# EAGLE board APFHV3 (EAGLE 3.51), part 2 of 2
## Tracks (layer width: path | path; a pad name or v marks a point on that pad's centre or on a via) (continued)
N$34  (via drill 0.05 pad 0.2) (continued)
  Bottom 0.1: v38.42,9.23 38.42,10.5 38.35,10.58 34,10.58 32.77,11.8 30.02,11.8 29.87,11.95 27.15,11.95 26.97,11.78 24.32,11.78 24.15,11.95 23.2,11.95 22.75,11.5 20.12,11.5 v19.3,12.33
N$35  (via drill 0.05 pad 0.2)
  Top 0.1: BARE_DIE. 38.07,6.2 38.62,6.75 38.62,9 v38.85,9.23 | v20.85,11.83 20.85,12.08
  Bottom 0.1: v38.85,9.23 38.85,10.58 38.65,10.78 34.17,10.78 32.95,12 30.15,12 30,12.15 27.02,12.15 26.85,11.98 24.5,11.98 24.32,12.15 22.97,12.15 22.57,11.75 20.92,11.75 v20.85,11.83
N$38
  Top 0.075: 13.4,0.8 13.4,0.4
N$39
  Top 0.075: 13.4,1.4 13.4,1
N$40
  Top 0.075: 13.9,0.9 13.5,0.9
N$41
  Top 0.075: 12.9,0.9 13.3,0.9
N$42
  Top 0.075: 13.9,18.7 13.5,18.7
N$43
  Top 0.075: 13.4,18.2 13.4,18.6
N$44
  Top 0.075: 12.9,18.7 13.3,18.7
N$45
  Top 0.075: 13.4,19.2 13.4,18.8
N$46
  Top 0.075: 73.2,18.2 73.2,18.6
N$47
  Top 0.075: 73.7,18.7 73.3,18.7
N$48
  Top 0.075: 72.7,18.7 73.1,18.7
N$49
  Top 0.075: 73.2,19.2 73.2,18.8
N$50
  Top 0.075: 73.2,1.23 73.2,1
N$51
  Top 0.075: 73.2,0.4 73.2,0.8
N$52
  Top 0.075: 73.7,0.9 73.3,0.9
N$53
  Top 0.075: 72.7,0.9 73.1,0.9
N$135
  Top 0.1: 39.45,13.1 40.35,13.1 40.35,12.3
NTC
  Top 0.1: 63.35,7.8 63.35,7.45 62.6,6.7 59.88,6.7 59.45,6.28 55,6.28 54.8,6.48 54.12,6.48 52.88,7.73 51.67,7.73 51.55,7.6 51.55,7.33 51.88,7 52.1,7 52.5,6.6 52.5,4.63 52.3,4.43 TR1.
NTC_RET
  Top 0.1: 61.85,7.8 61.85,7.45 61.57,7.18 59.88,7.18 59.2,6.5 55.2,6.5 54.97,6.73 54.2,6.73 52.95,7.98 51.2,7.98 50.7,7.48 50.7,6.1 50.82,5.98 51.55,5.98
RSIB  (via drill 0.05 pad 0.2)
  Top 0.1: 73.3,10.3 72.55,10.3 72.38,10.12 v72.38,9.05 | v60.35,8.48 60.35,7.8 | BARE_DIE.B 41.95,8.53 42.1,8.68 v42.1,8.88
  Bottom 0.1: v42.1,8.88 42.7,8.88 42.88,8.7 50.75,8.7 50.85,8.6 60.22,8.6 v60.35,8.48 60.4,8.43 71.75,8.43 v72.38,9.05
STRIN  (via drill 0.05 pad 0.2)
  Top 0.1: JPA_.1 v72.88,8.3 71.15,8.3 R1. | BARE_DIE.IN 41.65,8.73 v40.1,8.73 | 59.35,7.8 59.2,7.8 v58.97,8.03
  Bottom 0.1: v72.88,8.3 72.35,8.3 72.07,8.03 v58.97,8.03 58.8,8.2 50.3,8.2 50.2,8.3 42.67,8.3 42.62,8.35 42.17,8.35 41.88,8.05 40.25,8.05 40.1,8.2 v40.1,8.73
STRIP  (via drill 0.05 pad 0.2)
  Top 0.1: 73.3,8.8 v72.85,8.8 72.03,8.8 72.03,9 71.55,9.48 71.55,9.5 71.05,9.5 | v59.85,8.28 59.85,7.8 | BARE_DIE.IP 41.65,8.98 v41.02,8.98
  Bottom 0.1: v72.85,8.8 72.45,8.8 71.88,8.23 59.9,8.23 v59.85,8.28 59.82,8.28 59.7,8.4 50.5,8.4 50.4,8.5 42.77,8.5 42.72,8.55 41.45,8.55 41.15,8.25 40.5,8.25 40.38,8.38 40.38,8.85 40.5,8.98 v41.02,8.98
STRN  (via drill 0.05 pad 0.2)
  Top 0.075: 15.07,16.93 15.57,17.43 FE-7.2 | 22.67,16.93 23.17,17.43 FE-6.2 | 30.27,16.93 30.77,17.43 FE-5.2 | 37.88,16.93 38.38,17.43 FE-4.2 | 45.47,16.93 45.97,17.43 FE-3.2 | 53.07,16.93 53.57,17.43 FE-2.2 | 60.67,16.93 61.17,17.43 FE-1.2 | 68.28,16.93 68.78,17.43 FE-0.2 | 18.32,2.68 17.82,2.18 FE-8.2 | 25.92,2.68 25.42,2.18 FE-9.2 | 33.52,2.68 33.02,2.18 FE-10.2 | 41.12,2.68 40.62,2.18 FE-11.2 | 56.32,2.68 55.82,2.18 FE-13.2 | 63.92,2.68 63.42,2.18 FE-14.2 | 71.53,2.68 71.03,2.18 FE-15.2 | 48.72,2.68 48.22,2.18 FE-12.2
  Top 0.1: 21.72,3.95 21.72,3.9 v22.15,3.9 | v15.07,15.7 15.07,16.93 | v22.67,15.7 22.67,16.93 | v29,15.7 29.05,15.7 30.27,16.93 | v37.88,15.7 37.88,16.93 | v45.47,15.7 45.47,16.93 | v53.07,15.7 53.07,16.93 | v60.67,15.7 60.67,16.93 | v68.28,15.7 68.28,16.93 | 18.32,2.68 18.32,3.35 v18.87,3.9 | 25.92,2.68 v25.92,3.9 25.92,9.9 26.85,10.83 27.65,10.83 BARE_DIE.ON 28.35,10.78 28.42,10.85 v28.42,15.7 | 33.52,2.68 33.52,3.35 v34.07,3.9 | v41.12,3.9 41.12,2.68 | v56.32,3.9 56.32,2.68 | v63.92,3.9 63.92,2.68 | 71.53,2.68 v71.53,3.9 71.9,3.9 72.82,2.98 73.3,2.98 | v48.72,3.9 48.72,2.68
  Bottom 0.1: v71.53,3.9 v63.92,3.9 v56.32,3.9 v48.72,3.9 v41.12,3.9 v34.07,3.9 v25.92,3.9 v22.15,3.9 v18.87,3.9 | v15.07,15.7 v22.67,15.7 v28.42,15.7 v29,15.7 v37.88,15.7 v45.47,15.7 v53.07,15.7 v60.67,15.7 v68.28,15.7
STRP  (via drill 0.05 pad 0.2)
  Top 0.075: 14.82,17.02 15.42,17.62 FE-7.3 | 22.42,17.02 23.02,17.62 FE-6.3 | 30.05,17.05 30.62,17.62 FE-5.3 | 37.62,17.02 38.22,17.62 FE-4.3 | 52.82,17.02 53.42,17.62 FE-2.3 | 60.42,17.02 61.02,17.62 FE-1.3 | 68.03,17.02 68.62,17.62 FE-0.3 | 18.55,2.55 17.97,1.98 FE-8.3 | 26.17,2.58 25.57,1.98 FE-9.3 | 33.75,2.55 33.17,1.98 FE-10.3 | 41.38,2.58 40.77,1.98 FE-11.3 | 56.55,2.55 55.97,1.98 FE-13.3 | 64.15,2.55 63.57,1.98 FE-14.3 | 71.75,2.55 71.17,1.98 FE-15.3 | 48.95,2.55 48.38,1.98 FE-12.3 | FE-3.3 45.82,17.6 45.22,17
  Top 0.1: R16. 20.62,3.65 v19.22,3.65 18.55,2.98 18.55,2.55 | v14.82,15.95 14.82,17.02 | v22.42,15.95 22.42,17.02 | 30.05,17.05 28.95,15.95 v28.67,15.95 28.67,10.75 28.5,10.58 27.7,10.58 | v37.62,15.95 37.62,17.02 | v45.22,15.95 45.22,17 | v52.82,15.95 52.82,17.02 | v60.42,15.95 60.42,17.02 | v68.03,15.95 68.03,17.02 | 26.17,2.58 v26.17,3.65 26.17,9.8 26.95,10.58 27.7,10.58 | 33.75,2.55 33.75,2.98 v34.42,3.65 | v41.38,3.65 41.38,2.58 | 56.55,2.55 56.57,2.58 v56.57,3.65 | 64.15,2.55 64.17,2.58 v64.17,3.65 | 71.75,2.55 71.78,2.58 71.78,3.13 | v71.78,3.65 71.78,3.13 | JP2_.1 72.72,2.68 72.28,3.13 71.78,3.13 | 48.95,2.55 48.97,2.58 v48.97,3.65 | 27.7,10.58 BARE_DIE.OP
  Bottom 0.1: v71.78,3.65 v64.17,3.65 v56.57,3.65 v48.97,3.65 v41.38,3.65 v34.42,3.65 v26.17,3.65 v19.22,3.65 | v14.82,15.95 v22.42,15.95 v28.67,15.95 v37.62,15.95 v45.22,15.95 v52.82,15.95 v60.42,15.95 v68.03,15.95
SYNCN  (via drill 0.05 pad 0.2)
  Top 0.075: 16.57,16.75 16.47,16.85 16.47,18.05 | 24.17,16.75 24.07,16.85 24.07,18.05 | 31.77,16.75 31.67,16.85 31.67,18.05 | 39.38,16.75 39.27,16.85 39.27,18.05 | 46.97,16.75 46.88,16.85 46.88,18.05 | 54.57,16.75 54.47,16.85 54.47,18.05 | 62.17,16.75 62.07,16.85 62.07,18.05 | 69.78,16.75 69.67,16.85 69.67,18.05 | 16.82,2.85 16.92,2.75 16.92,1.55 | 24.42,2.85 24.52,2.75 24.52,1.55 | 32.02,2.85 32.12,2.75 32.12,1.55 | 39.62,2.85 39.72,2.75 39.72,1.55 | 62.42,2.85 62.52,2.75 62.52,1.55 | 47.22,2.85 47.32,2.75 47.32,1.55 | 54.82,2.85 54.92,2.75 54.92,1.55 | 70.03,2.85 70.12,2.75 70.12,1.55
  Top 0.1: v28.62,5.4 28.62,8.58 | 28.62,8.58 28.95,8.58 29.42,9.05 v29.42,14.2 | 28.62,8.58 BARE_DIE.CN | 24.95,12.53 24.97,12.5 24.97,13.08 24.17,13.88 v24.17,14.2 24.17,16.75 | v16.57,14.2 16.57,16.75 | v31.92,14.2 31.92,14.98 31.77,15.12 31.77,16.75 | v39.38,14.2 39.38,16.75 | v46.97,14.2 46.97,16.75 | v54.57,14.2 54.57,16.75 | v62.17,14.2 62.17,16.75 | v69.78,14.2 69.78,16.75 | v16.82,4.28 16.82,2.85 | v24.42,5.4 24.42,2.85 | v31.22,5.4 31.22,4.53 32.02,3.73 32.02,2.85 | v39.62,5.4 39.62,2.85 | v54.82,5.4 54.82,2.85 | v62.42,5.4 62.42,2.85 | 70.03,2.85 v70.03,5.4 71.95,5.4 72.57,4.78 73.3,4.78 | v47.22,5.4 47.22,2.85
  Bottom 0.1: v16.57,14.2 v24.17,14.2 v29.42,14.2 v31.92,14.2 v39.38,14.2 v46.97,14.2 v54.57,14.2 v62.17,14.2 v69.78,14.2 | v70.03,5.4 v62.42,5.4 v54.82,5.4 v47.22,5.4 v39.62,5.4 v31.22,5.4 v28.62,5.4 v24.42,5.4 17.05,5.4 16.82,5.18 v16.82,4.28
SYNCP  (via drill 0.05 pad 0.2)
  Top 0.075: 16.32,16.45 16.32,18.05 | 23.92,16.45 23.92,18.05 | 31.52,16.45 31.52,18.05 | 39.12,16.45 39.12,18.05 | 46.72,16.45 46.72,18.05 | 54.32,16.45 54.32,18.05 | 61.92,16.45 61.92,18.05 | 69.53,16.45 69.53,18.05 | 17.07,3.15 17.07,1.55 | 24.67,3.15 24.67,1.55 | 32.27,3.15 32.27,1.55 | 39.88,3.15 39.88,1.55 | 47.47,3.15 47.47,1.55 | 55.07,3.15 55.07,1.55 | 62.67,3.15 62.67,1.55 | 70.28,3.15 70.28,1.55
  Top 0.1: v31.92,5.15 31.92,4.53 32.27,4.18 32.27,3.15 | v16.32,14.45 16.32,16.45 | BARE_DIE.CP 27.7,8.33 v28.12,8.33 28.37,8.08 v28.37,5.15 | v29.67,9.15 v29.67,14.45 | 23.92,16.45 v23.92,14.45 23.92,12.6 R13. 23.85,12.5 | 31.52,16.45 31.52,15.5 31.2,15.18 v31.2,14.45 | v39.12,14.45 39.12,16.45 | v46.72,14.45 46.72,16.45 | v54.32,14.45 54.32,16.45 | v61.92,14.45 61.92,16.45 | v69.53,14.45 69.53,16.45 | v17.07,4.08 17.07,3.15 | v24.67,5.15 24.67,3.15 | v39.88,5.15 39.88,3.15 | v55.07,5.15 55.07,3.15 | v62.67,5.15 62.67,3.15 | v70.28,5.15 70.28,3.15 | v73,4.48 JP2_. | v47.47,5.15 47.47,3.15
  Bottom 0.1: v16.32,14.45 v23.92,14.45 v29.67,14.45 v31.2,14.45 v39.12,14.45 v46.72,14.45 v54.32,14.45 v61.92,14.45 v69.53,14.45 | v28.12,8.33 28.85,8.33 v29.67,9.15 | v17.07,4.08 17.07,4.83 17.4,5.15 v24.67,5.15 v28.37,5.15 v31.92,5.15 v39.88,5.15 v47.47,5.15 v55.07,5.15 v62.67,5.15 v70.28,5.15 70.88,5.15 71.55,4.48 v73,4.48
TS1
  Top 0.2: 4.5,18.3 3.9,18.3 | 1.5,1.9 1.5,1.3
  Top 1: 1.5,18.27 1.5,18.3 | 1.5,18.27 1.5,1.9 | 1.5,18.27 1.52,18.27 | 1.5,18.27 1.52,18.3 3.9,18.3
TS3
  Bottom 0.1: 1.9,0.8 1.9,17.8 5.5,17.8
  Bottom 0.2: 1.9,0.8 1.9,0.83
TS-2
  Top 0.1: 2.6,0.5 2.6,17.5 6.2,17.5
TS-VIA1  (via drill 0.05 pad 0.2)
  Top 0.1: v3.6,16.2 3.6,16 3.9,16 v3.9,16.2 | v3.6,16.5 3.6,16.7 | v3.9,16.5 3.9,16.7 4.2,16.7 v4.2,16.5 | v4.2,16.2 4.2,16 4.5,16 v4.5,16.2 | v4.5,16.5 4.5,16.7 4.8,16.7 v4.8,16.5 | v4.8,16.2 4.8,16 5.1,16 v5.1,16.2 | v5.1,16.5 5.1,16.7 5.4,16.7 v5.4,16.5 | v5.4,16.2 5.4,16 5.7,16 v5.7,16.2 | v5.7,16.5 5.7,16.7 6,16.7 v6,16.5 | v6,16.2 6,16 6.3,16 v6.3,16.2 | v6.3,16.5 6.3,16.7 6.6,16.7 v6.6,16.5 | v6.6,16.2 6.6,16 6.9,16 v6.9,16.2 | v6.9,16.5 6.9,16.7 7.2,16.7 v7.2,16.5 | v7.2,16.2 7.2,16 7.5,16 v7.5,16.2 | v7.5,16.5 7.5,16.7 7.8,16.7 v7.8,16.5 | v7.8,16.2 7.8,16 8.1,16 v8.1,16.2 | v8.1,16.5 8.1,16.7
  Bottom 0.1: v3.6,16.2 v3.6,16.5 | v3.9,16.5 v3.9,16.2 | v4.2,16.2 v4.2,16.5 | v4.5,16.5 v4.5,16.2 | v4.8,16.2 v4.8,16.5 | v5.1,16.5 v5.1,16.2 | v5.4,16.2 v5.4,16.5 | v5.7,16.5 v5.7,16.2 | v6,16.2 v6,16.5 | v6.3,16.5 v6.3,16.2 | v6.6,16.2 v6.6,16.5 | v6.9,16.5 v6.9,16.2 | v7.2,16.2 v7.2,16.5 | v7.5,16.5 v7.5,16.2 | v7.8,16.2 v7.8,16.5 | v8.1,16.5 v8.1,16.2
TS-VIA2  (via drill 0.05 pad 0.2)
  Top 0.1: v3.6,15.08 3.6,14.88 3.9,14.88 v3.9,15.08 | v3.6,15.38 3.6,15.58 | v3.9,15.38 3.9,15.58 4.2,15.58 v4.2,15.38 | v4.2,15.08 4.2,14.88 4.5,14.88 v4.5,15.08 | v4.5,15.38 4.5,15.58 4.8,15.58 v4.8,15.38 | v4.8,15.08 4.8,14.88 5.1,14.88 v5.1,15.08 | v5.1,15.38 5.1,15.58 5.4,15.58 v5.4,15.38 | v5.4,15.08 5.4,14.88 5.7,14.88 v5.7,15.08 | v5.7,15.38 5.7,15.58 6,15.58 v6,15.38 | v6,15.08 6,14.88 6.3,14.88 v6.3,15.08 | v6.3,15.38 6.3,15.58 6.6,15.58 v6.6,15.38 | v6.6,15.08 6.6,14.88 6.9,14.88 v6.9,15.08 | v6.9,15.38 6.9,15.58 7.2,15.58 v7.2,15.38 | v7.2,15.08 7.2,14.88 7.5,14.88 v7.5,15.08 | v7.5,15.38 7.5,15.58 7.8,15.58 v7.8,15.38 | v7.8,15.08 7.8,14.88 8.1,14.88 v8.1,15.08 | v8.1,15.38 8.1,15.58
  Bottom 0.1: v3.6,15.08 v3.6,15.38 | v3.9,15.38 v3.9,15.08 | v4.2,15.08 v4.2,15.38 | v4.5,15.38 v4.5,15.08 | v4.8,15.08 v4.8,15.38 | v5.1,15.38 v5.1,15.08 | v5.4,15.08 v5.4,15.38 | v5.7,15.38 v5.7,15.08 | v6,15.08 v6,15.38 | v6.3,15.38 v6.3,15.08 | v6.6,15.08 v6.6,15.38 | v6.9,15.38 v6.9,15.08 | v7.2,15.08 v7.2,15.38 | v7.5,15.38 v7.5,15.08 | v7.8,15.08 v7.8,15.38 | v8.1,15.38 v8.1,15.08
TS-VIA-3
  Top 0.1: 3.62,14.45 3.62,13.75 3.92,13.75 3.92,14.45 4.22,14.45 4.22,13.75 4.52,13.75 4.52,14.45 4.82,14.45 4.82,13.75 5.12,13.75 5.12,14.45 5.42,14.45 5.42,13.75 5.72,13.75 5.72,14.45 6.02,14.45 6.02,13.75 6.32,13.75 6.32,14.45 6.62,14.45 6.62,13.75 6.92,13.75 6.92,14.45 7.22,14.45 7.22,13.75 7.52,13.75 7.52,14.45 7.82,14.45 7.82,13.75 8.12,13.75 8.12,14.45
VCAL  (via drill 0.05 pad 0.2)
  Top 0.075: 17.37,19.4 17.37,18.05
  Top 0.1: 73.3,13.3 v72.82,13.3 72.82,17.3 72.5,17.62 72.5,19.4 70.57,19.4 | 54.02,0.3 61.62,0.3 | 54.02,0.3 46.42,0.3 | 46.42,0.3 38.82,0.3 | 38.82,0.3 31.22,0.3 | 31.22,0.3 23.62,0.3 | 23.62,0.3 16.02,0.3 16.02,1.55 | 70.57,19.4 62.97,19.4 | 62.97,19.4 55.38,19.4 | 55.38,19.4 47.77,19.4 | 47.77,19.4 40.17,19.4 | 40.17,19.4 32.57,19.4 | 32.57,19.4 24.97,19.4 | 24.97,19.4 17.37,19.4 | 61.62,0.3 69.22,0.3 | 69.22,0.3 72.28,0.3 72.5,0.53 v72.5,1.78 | v53.85,7.45 53.85,7.8 | v66.07,6.95 65.72,7.3 64.45,7.3 64.25,7.1 63.7,7.1 v63.55,7.25 | 54.02,1.55 54.02,0.3 | 55.38,19.4 55.38,18.05 | 62.97,19.4 62.97,18.05 | 70.57,19.4 70.57,18.05 | 47.77,19.4 47.77,18.05 | 40.17,19.4 40.17,18.05 | 32.57,19.4 32.57,18.05 | 24.97,19.4 24.97,18.05 | 23.62,0.3 23.62,1.55 | 31.22,0.3 31.22,1.55 | 38.82,0.3 38.82,1.55 | 46.42,0.3 46.42,1.55 | 61.62,0.3 61.62,1.55 | 69.22,0.3 69.22,1.55
  Bottom 0.1: 73.4,5.93 73.4,2.68 v72.5,1.78 | 73.4,5.93 73.4,12.88 72.97,13.3 v72.82,13.3 | v53.85,7.45 54.1,7.2 63.5,7.2 v63.55,7.25 | v66.07,6.95 66.17,6.85 66.9,6.85 66.97,6.93 71.53,6.93 72.53,5.93 73.4,5.93
VDD  (via drill 0.05 pad 0.2)
  Top 0.1: v71.32,18.4 71.32,18.05 | v68.47,18.35 FE-0.4 | v63.72,18.5 63.72,18.05 | v40.92,18.5 40.92,18.05 | v45.67,18.45 FE-3.4 | v60.88,18.5 FE-1.4 | v56.12,18.5 56.12,18.05 | v53.27,18.5 FE-2.4 | v48.52,18.5 48.52,18.05 | v38.07,18.5 FE-4.4 | v33.32,18.5 33.32,18.05 | v30.47,18.5 FE-5.4 | v25.72,18.5 25.72,18.05 | v22.87,18.5 FE-6.4 | v18.12,18.5 18.12,18.05 | v15.27,18.5 FE-7.4 | v15.27,1.1 15.27,1.55 | v18.12,1.1 FE-8.4 | v22.87,1.1 22.87,1.55 | v25.72,1.12 FE-9.4 | v30.47,1.1 30.47,1.55 | v33.32,1.1 FE-10.4 | v38.07,1.1 38.07,1.55 | v45.67,1.1 45.67,1.55 | v40.92,1.1 FE-11.4 | v48.52,1.1 FE-12.4 | 53.27,1.55 v53.27,1.12 | v56.12,1.1 FE-13.4 | v60.88,1.1 60.88,1.55 | v63.72,1.1 FE-14.4 | v68.47,1.1 68.47,1.55 | v71.32,1.1 FE-15.4 | v72.92,1.78 JP2_.7
  Top 0.35: 44.15,10.8 44.15,10.48 43.55,9.85
  Top 0.4: v71.1,12 71.3,11.8 73.3,11.8 | v49.7,11.85 49.7,12.58
  Top 0.5: v57.35,12 57.35,7.8 | 44.15,10.8 v45.6,10.8 45.6,13.95 43.3,16.25 v43.3,18.23 43.3,18.83 42.5,18.83 | C2. 49.7,14.1 49.7,12.58 C21. | 65.32,18.83 66.1,18.83 v66.1,18.23 | 57.72,18.83 58.4,18.83 58.5,18.73 v58.5,18.23 | 50.12,18.83 50.9,18.83 v50.9,18.23 | 34.92,18.83 35.7,18.83 v35.7,18.23 | 27.32,18.83 28.1,18.83 v28.1,18.23 | 19.72,18.83 20.5,18.83 v20.5,18.23 | 21.3,1 20.5,1 v20.5,1.38 | 28.87,1 28.12,1 v28.12,1.38 | 36.47,1 35.72,1 v35.72,1.38 | 43.55,9.85 43.55,2.98 43.3,2.73 v43.3,1.38 43.3,1 44.07,1 | 51.67,1 50.9,1 v50.9,1.38 | 59.27,1 58.5,1 v58.5,1.38 | 66.88,1 66.1,1 v66.1,1.38
  Bottom 0: v71.32,18.4 71.32,18.23 72.03,18.23 | 63.72,18.23 v63.72,18.5 | 40.92,18.23 v40.92,18.5 | 45.67,18.23 v45.67,18.45 | 60.88,18.23 v60.88,18.5 | 56.12,18.23 v56.12,18.5 | 53.27,18.23 v53.27,18.5 | 48.52,18.23 v48.52,18.5 | 38.07,18.23 v38.07,18.5 | 33.32,18.23 v33.32,18.5 | 30.47,18.23 v30.47,18.5 | 25.72,18.23 v25.72,18.5 | 22.87,18.23 v22.87,18.5 | 18.12,18.23 v18.12,18.5 | 15.27,18.23 v15.27,18.5 | 15.27,1.38 v15.27,1.1 | 18.12,1.38 v18.12,1.1 | 22.87,1.38 v22.87,1.1 | 25.72,1.38 v25.72,1.12 | 30.47,1.38 v30.47,1.1 | 33.32,1.38 v33.32,1.1 | 38.07,1.38 v38.07,1.1 | 45.67,1.38 v45.67,1.1 | 40.92,1.38 v40.92,1.1 | 48.52,1.38 v48.52,1.1 | v53.27,1.12 53.27,1.38 | 56.12,1.38 v56.12,1.1 | 60.88,1.38 v60.88,1.1 | 63.72,1.38 v63.72,1.1 | 68.47,1.38 v68.47,1.1 | 71.32,1.38 v71.32,1.1
  Bottom 0.1: 68.47,18.23 v68.47,18.35 | 72,1.38 72.53,1.38 v72.92,1.78
  Bottom 0.3: 52.3,11.43 52.6,11.43 53.07,11.9 53.07,12
  Bottom 0.4: 49.7,10.8 v49.7,11.85
  Bottom 0.5: v71.1,12 v57.35,12 53.07,12 51.88,10.8 49.7,10.8 v45.6,10.8
  Bottom 0.75: 14.37,18.23 15.27,18.23 18.12,18.23 v20.5,18.23 22.87,18.23 25.72,18.23 v28.1,18.23 30.47,18.23 33.32,18.23 v35.7,18.23 38.07,18.23 40.92,18.23 v43.3,18.23 45.67,18.23 48.52,18.23 v50.9,18.23 53.27,18.23 56.12,18.23 v58.5,18.23 60.88,18.23 63.72,18.23 v66.1,18.23 68.47,18.23 72.03,18.23 72.07,18.23 | 72,1.38 71.32,1.38 68.47,1.38 v66.1,1.38 63.72,1.38 60.88,1.38 v58.5,1.38 56.12,1.38 53.27,1.38 v50.9,1.38 48.52,1.38 45.67,1.38 v43.3,1.38 40.92,1.38 38.07,1.38 v35.72,1.38 33.32,1.38 30.47,1.38 v28.12,1.38 25.72,1.38 22.87,1.38 v20.5,1.38 18.12,1.38 15.27,1.38 14.5,1.38
VDD_AMS  (via drill 0.05 pad 0.2)
  Top 0.1: v42.47,8.1 42.32,7.95 41.72,7.95 | 34.97,14 BARE_DIE._2 | v28.07,7.68 BARE_DIE._5 | v28.6,9.88 BARE_DIE._4 | BARE_DIE._3 27.7,11.53 27.77,11.45 v27.92,11.45 | BARE_DIE._1 41.15,10.08
  Top 0.2: 34.97,14 34.97,12.55 34.7,12.28 v34.7,10.3
  Top 0.25: 35.57,7.2 BARE_DIE._0
  Top 0.4: v72.22,12.8 73.3,12.8 | 41.67,7.95 39.85,7.95 39.85,8.15 v39.27,8.73 40.62,10.08 41.15,10.08 | 35.57,7.23 v35.57,8.65 35.57,7.2 | 41.67,7.95 41.72,7.95 | C5. 41.45,7.95 41.67,7.95 | v45.67,8.05 46.02,8.4
  Top 0.5: 54.35,8.4 54.35,7.8 | 54.35,8.4 v54.35,10.2 | 46.02,8.4 54.35,8.4 | C1. 68.12,9.2 68.4,9.48 v68.4,10.2
  Bottom 0: 34.5,8.65 34.67,8.65 34.7,8.68
  Bottom 0.1: v28.07,7.68 29.5,7.68 29.95,8.12 31.12,8.12 31.67,8.68 | v27.92,11.45 30.02,11.45 31.12,10.35 31.12,9.88 | 31.12,9.88 31.12,9.23 31.67,8.68 | 31.12,9.88 v28.6,9.88 | 31.7,8.65 31.67,8.68
  Bottom 0.2: 34.7,8.68 v34.7,10.3 | v45.67,8.05 42.52,8.05 v42.47,8.1
  Bottom 0.4: 34.5,8.65 v35.57,8.65 35.57,8.68 35.62,8.73 v39.27,8.73
  Bottom 0.5: v72.22,12.8 72.22,10.75 71.67,10.2 v68.4,10.2 v54.35,10.2 | 34.5,8.65 31.7,8.65
VDDA  (via drill 0.05 pad 0.2)
  Top 0: 44.75,8.08 44.75,8.15 44.92,8.15 C6. | 28.87,16.83 28.9,16.8 v28.87,16.8 | v51.67,16.8 51.65,16.83 51.67,16.83 | 67.95,18.05 FE-0.8 | 64.25,18.05 64.32,18.05 | 56.65,18.05 56.72,18.05 | FE-1.8 FE-1.7 | 49.2,17.4 49.05,17.4 | 49.05,18.05 49.12,18.05 | 41.45,18.05 41.38,18.05 | 36.5,17.58 36.5,17.55 36.47,17.52 | 33.77,18.05 33.92,18.05 33.85,18.05 | 33.85,17.35 33.85,17.38 34,17.38 | 29.95,18.05 FE-5.8 | 18.57,18.05 18.72,18.05 18.65,18.05 | 18.8,17.38 18.65,17.38 | 14.67,1.55 14.75,1.55 14.82,1.55 | 22.35,1.55 22.42,1.55 | 22.35,1.55 22.32,1.58 22.3,1.55 22.27,1.55 22.35,1.55 | 22.2,2.23 22.35,2.23 | 30.02,1.55 29.87,1.55 29.95,1.55 | 37.62,1.55 37.47,1.55 37.55,1.55 | 37.4,2.23 37.55,2.23 | 45.15,1.58 45.07,1.55 | 52.82,1.55 52.75,1.55 52.67,1.55 | 52.75,2.23 52.6,2.23 | 60.42,1.55 60.35,1.55 60.27,1.55 | 60.2,2.23 60.35,2.23 | 26.17,18.05 26.32,18.05 26.25,18.05 | 26.4,17.38 26.25,17.38
  Top 0.075: 26.52,2.1 26.32,1.9 FE-9.8 | 34.12,2.1 33.92,1.9 FE-10.8 | 49.32,2.1 49.12,1.9 FE-12.8 | 56.92,2.1 56.72,1.9 FE-13.8 | 64.53,2.1 64.32,1.9 FE-14.8 | v42.52,2.8 42.52,2.1 42.35,1.93 | 41.65,1.93 41.52,1.8 FE-11.8 | 67.88,2.1 67.88,1.55
  Top 0.1: 51.67,17.52 52.5,17.52 52.67,17.7 FE-2.8 FE-2.7 | 21.27,17.52 22.1,17.52 22.27,17.7 FE-6.8 FE-6.7 | 18.95,2.1 18.72,1.9 FE-8.8 FE-8.7 | JP2_.3 73.1,2.38 73,2.48 72.17,2.48 | 44.1,17.73 44.12,17.7 44.15,17.7 44.2,17.65 44.95,17.65 45.07,17.77 FE-3.8 FE-3.7 | 42.35,1.93 41.65,1.93 | 14.42,17.45 14.67,17.7 FE-7.8 FE-7.7 | 71.92,1.95 FE-15.8 FE-15.7 | FE-1.8 60.35,18.05 60.35,17.7 60.27,17.62 59.3,17.62 | 71.78,18.05 71.92,18.05 71.85,18.05 | FE-0.7 67.95,18.05 67.95,17.75 67.8,17.6 66.88,17.6 | 64.32,18.05 64.17,18.05 | 64.4,17.38 64.25,17.38 | 56.72,18.05 56.57,18.05 | 49.12,18.05 48.97,18.05 | 41.52,18.05 41.45,18.05 41.45,17.48 41.25,17.27 | 37.55,18.05 FE-4.8 | 37.55,18.05 FE-4.7 | 37.55,18.05 37.55,17.7 37.42,17.58 36.5,17.58 | FE-5.8 FE-5.7 | 29.95,18.05 29.95,17.7 29.87,17.62 28.87,17.62 | FE-9.8 FE-9.7 | 27.02,5.23 27,3.33 v26.75,3.08 | FE-10.8 FE-10.7 | FE-11.8 FE-11.7 | 45.07,1.55 45.22,1.55 | FE-12.8 FE-12.7 | FE-13.8 FE-13.7 | FE-14.8 FE-14.7 | 67.88,1.55 68.03,1.55
  Top 0.2: 19.72,2.1 18.95,2.1 | 27.32,2.1 26.52,2.1 | 34.92,2.1 34.12,2.1 | 50.12,2.1 49.32,2.1 | 57.72,2.1 56.92,2.1 | 65.32,2.1 64.53,2.1 | 71.92,1.95 72.17,2.2 72.17,2.48 v72.17,2.8 | v14.42,16.8 14.42,17.45 | v71.85,16.8 71.85,18.05 | 64.25,17.38 64.25,18.05 | 56.8,17.38 56.65,17.38 56.65,18.05 | 49.05,17.4 49.05,18.05 | 33.85,17.38 33.85,18.05 | 18.65,17.38 18.65,18.05 | 22.35,2.23 22.35,1.55 | 29.95,2.23 29.95,2.2 29.95,1.55 | 37.55,2.23 37.55,1.55 | 45.15,2.1 45.15,1.58 | 52.75,1.55 52.75,2.23 | 60.35,2.23 60.35,1.55 | 26.25,17.38 26.25,18.05
  Top 0.25: v14.75,2.8 14.75,1.55
  Top 0.3: v41.25,16.52 41.25,17.27
  Top 0.4: v29.95,2.8 29.95,2.2 | 45.15,3 45.15,2.1 | v71.12,10.8 73.3,10.8
  Top 0.5: v66.88,16.8 66.88,17.6 66.88,17.73 | v64.4,16.8 64.4,17.38 | v59.27,16.8 59.3,17.62 59.27,17.73 | v56.8,16.8 56.8,17.38 | 51.67,16.83 51.67,17.52 51.67,17.73 | v49.2,16.8 49.2,17.4 | v36.47,16.8 36.47,17.52 36.47,17.73 | v34,16.8 34,17.38 | 28.87,16.83 28.87,17.62 28.87,17.73 | v26.4,16.8 26.4,17.38 | v21.27,16.8 21.27,17.52 21.27,17.73 | v18.8,16.8 18.8,17.38 | v19.72,2.8 19.72,2.1 | v22.2,2.8 22.2,2.23 | v27.32,2.8 27.32,2.1 | v34.92,2.8 34.92,2.1 | v37.4,2.8 37.4,2.23 | 45.15,3 v45.07,3.08 44.75,3.4 44.75,8.08 46.25,9.58 | v50.12,2.8 50.12,2.1 | 52.6,2.23 v52.6,2.8 | v57.72,2.8 57.72,2.1 | v60.2,2.8 60.2,2.23 | v65.32,2.8 65.32,2.1 | v67.88,2.8 67.88,2.1 | 55.35,7.8 v55.35,10.8 53.92,10.8 52.72,9.6 52.72,9.58 C3. 46.25,9.58 | 44.1,17.73 v44.1,16.52 44.1,16.4 46.25,14.25 46.25,9.58
  Bottom 0: 36.47,3.08 36.47,2.8 | 34.05,3.08 34.3,2.8 | 37.12,16.8 37.12,16.15 | 21.92,16.8 21.92,16.15 | 18.72,16.52 v18.8,16.8 v21.27,16.8 21.92,16.8 | 44.72,16.8 44.72,16.15 | v59.27,16.8 59.92,16.15 | 56.72,16.52 v56.8,16.8 | v56.8,16.8 v59.27,16.8 | 67.53,16.15 v66.88,16.8 v64.4,16.8 | v64.4,16.8 64.32,16.52 | v59.27,16.8 v64.4,16.8 | v56.8,16.8 v59.27,16.8 | v49.2,16.8 52.32,16.8 52.32,16.15 51.67,16.83 | v41.25,16.52 44.72,16.8 | 37.12,16.8 v34,16.8 | v71.85,16.8 71.92,16.52 71.9,16.52 71.88,16.5 71.85,16.52 71.82,16.52 | 29.52,16.8 29.52,16.15 | v26.4,16.8 26.32,16.52 | 37.12,16.8 29.52,16.8 | v26.4,16.8 v28.87,16.8 29.52,16.8 | v26.4,16.8 21.92,16.8 | v49.2,16.8 49.12,16.52 | v49.2,16.8 v51.67,16.8 | v56.8,16.8 51.67,16.83 | v49.2,16.8 v51.67,16.8 | v51.67,16.8 51.67,16.83 | v49.2,16.8 44.72,16.8 | v49.2,16.8 v44.1,16.52 44.22,16.8 v41.25,16.52 | v41.25,16.52 37.12,16.8 | 33.92,16.52 v34,16.8 | v36.47,16.8 v34,16.8 | v41.25,16.52 v36.47,16.8 | v36.47,16.8 v34,16.8 | v34,16.8 29.52,16.8 | 19.07,2.8 19.07,3.45 | 22.27,3.08 v22.2,2.8 | 19.07,2.8 v14.75,2.8 | v22.2,2.8 v19.72,2.8 19.07,2.8 | v22.2,2.8 v27.32,2.8 | 28.45,3.35 29.87,3.08 v29.95,2.8 v34.92,2.8 | 36.05,3.35 37.47,3.08 v37.4,2.8 | 44.07,3.08 44.07,2.8 | 41.65,3.08 41.9,2.8 | 43.65,3.35 v45.07,3.08 v50.12,2.8 | 51.67,3.08 51.67,2.8 | 49.25,3.08 49.5,2.8 | 51.25,3.35 52.67,3.08 v52.6,2.8 v57.72,2.8 | 59.27,3.08 59.27,2.8 | 56.85,3.08 57.1,2.8 | 58.85,3.35 60.27,3.08 v60.2,2.8 v65.32,2.8 | 66.88,3.08 66.88,2.8 | 64.45,3.08 64.7,2.8 | 66.45,3.35 67.88,3.08 v67.88,2.8 | 71.95,3.08 71.95,3.05 v72.17,2.8 72.15,2.83 72.15,2.98 72.05,3.08 | 71.92,3.08 72,3.08
  Bottom 0.075: 52.32,16.8 v56.8,16.8 | v37.4,2.8 v42.52,2.8
  Bottom 0.2: 14.67,16.52 14.65,16.52 14.42,16.75 v14.42,16.8 | 44.22,16.8 43.92,16.8
  Bottom 0.5: v55.35,10.8 v71.12,10.8
  Bottom 0.75: 67.88,3.08 36.47,3.08 34.05,3.08 29.87,3.08 | v26.75,3.08 29.87,3.08 | v26.75,3.08 14.67,3.08 | 33.92,16.52 14.67,16.52 | v44.1,16.52 71.82,16.52 | 33.92,16.52 v41.25,16.52 v44.1,16.52 | v44.1,16.52 56.72,16.52 | 33.92,16.52 18.72,16.52 | 37.47,3.08 41.65,3.08 44.07,3.08 | 37.47,3.08 v26.75,3.08 | v26.75,3.08 22.27,3.08 | v45.07,3.08 49.25,3.08 51.67,3.08 | 29.87,3.08 v45.07,3.08 | 52.67,3.08 56.85,3.08 59.27,3.08 | 52.67,3.08 37.47,3.08 | v45.07,3.08 60.27,3.08 64.45,3.08 66.88,3.08 | 67.88,3.08 71.92,3.08 71.95,3.08 72,3.08 72.05,3.08 | 52.67,3.08 67.88,3.08
VDET
  Top 0.25: HV_PT1. 19.8,9.3 R7.
VDET_RET
  Top 0.25: R5. 23,9.23 21.47,9.23 HV_PT2.
WB-L
  Top 0.1: 5.22,2.95 3.2,2.95 | 5.22,3.2 3.2,3.2 3.2,3.45 5.2,3.45 5.2,3.7 3.2,3.7 3.2,3.95 5.2,3.95 5.2,4.2 3.2,4.2 3.2,4.45 5.2,4.45 5.2,4.7 3.2,4.7 3.2,4.95 5.2,4.95 5.2,5.2 3.2,5.2 3.2,5.45 5.2,5.45 5.2,5.7 3.2,5.7 3.2,5.95 5.2,5.95 5.2,6.2 3.2,6.2 3.2,6.45 5.2,6.45 5.2,6.7 3.2,6.7 3.2,6.95 5.2,6.95 5.2,7.2 3.2,7.2 3.2,7.45 5.2,7.45 5.2,7.7 3.2,7.7 3.2,7.95 5.2,7.95 5.2,8.2 3.2,8.2 3.2,8.45 5.2,8.45 5.2,8.7 3.2,8.7 3.2,8.95 5.2,8.95 5.2,9.2 3.2,9.2 3.2,9.45 5.2,9.45 5.2,9.7 3.2,9.7 3.2,9.95 5.2,9.95 5.2,10.2 3.2,10.2 3.2,10.45 5.2,10.45 5.2,10.7 3.2,10.7 | 5.22,3.2 5.2,3.2 | 5.22,2.95 5.2,2.95 | 5.22,3.2 5.22,2.95
WB-R
  Top 0.1: 8.2,10.7 6.2,10.7 6.2,10.45 8.2,10.45 8.2,10.2 6.2,10.2 6.2,9.95 8.2,9.95 8.2,9.7 6.2,9.7 6.2,9.45 8.2,9.45 8.2,9.2 6.2,9.2 6.2,8.95 8.2,8.95 8.2,8.7 6.2,8.7 6.2,8.45 8.2,8.45 8.2,8.2 6.2,8.2 6.2,7.95 8.2,7.95 8.2,7.7 6.2,7.7 6.2,7.45 8.2,7.45 8.2,7.2 6.2,7.2 6.2,6.95 8.2,6.95 8.2,6.7 6.2,6.7 6.2,6.45 8.2,6.45 8.2,6.2 6.2,6.2 6.2,5.95 8.2,5.95 8.2,5.7 6.2,5.7 6.2,5.45 8.2,5.45 8.2,5.2 6.2,5.2 6.2,4.95 8.2,4.95 8.2,4.7 6.2,4.7 6.2,4.45 8.2,4.45 8.2,4.2 6.2,4.2 6.2,3.95 8.2,3.95 8.2,3.7 6.2,3.7 6.2,3.45 8.2,3.45 8.2,3.2 6.2,3.2 6.2,2.95 8.2,2.95
XCKN  (via drill 0.05 pad 0.2)
  Top 0.075: 16.07,16.55 16.17,16.65 16.17,18.05 | 23.67,16.55 23.77,16.65 23.77,18.05 | 31.27,16.55 31.37,16.65 31.37,18.05 | 38.88,16.55 38.97,16.65 38.97,18.05 | 46.47,16.55 46.57,16.65 46.57,18.05 | 54.07,16.55 54.17,16.65 54.17,18.05 | 61.67,16.55 61.77,16.65 61.77,18.05 | 69.28,16.55 69.38,16.65 69.38,18.05 | 17.32,3.05 17.22,2.95 17.22,1.55 | 24.92,3.05 24.82,2.95 24.82,1.55 | 32.52,3.05 32.42,2.95 32.42,1.55 | 40.12,3.05 40.02,2.95 40.02,1.55 | 55.32,3.05 55.22,2.95 55.22,1.55 | 62.92,3.05 62.82,2.95 62.82,1.55 | 70.53,3.05 70.42,2.95 70.42,1.55 | 47.72,3.05 47.62,2.95 47.62,1.55
  Top 0.1: BARE_DIE.INN 27.75,9.03 28.3,9.03 v28.3,9.43 | v28.3,9.43 27.75,9.43 27.7,9.38 | v28.3,9.43 28.92,9.43 v28.92,14.7 | 23.85,11.48 23.6,11.48 23.22,11.85 23.22,13.03 23.67,13.48 v23.67,14.7 23.67,16.55 | v16.07,14.7 16.07,16.55 | v30.45,14.7 30.45,15.18 31.27,16 31.27,16.55 | v38.88,14.7 38.88,16.55 | v46.47,14.7 46.47,16.55 | v54.07,14.7 54.07,16.55 | v61.67,14.7 61.67,16.55 | v69.28,14.7 69.28,16.55 | v17.32,3.9 17.32,3.05 | 24.92,3.05 v24.92,4.9 v24.92,9.33 | v32.65,4.9 32.65,4.65 32.52,4.53 32.52,3.05 | v40.12,4.9 40.12,3.05 | v55.32,4.9 55.32,3.05 | v62.92,4.9 62.92,3.05 | 70.53,3.05 v70.53,4.9 72.12,4.9 72.85,4.18 73.3,4.18 | v47.72,4.9 47.72,3.05
  Bottom 0.1: v70.53,4.9 v62.92,4.9 v55.32,4.9 v47.72,4.9 v40.12,4.9 v32.65,4.9 v24.92,4.9 17.75,4.9 17.35,4.5 17.35,3.9 v17.32,3.9 | v16.07,14.7 v23.67,14.7 v28.92,14.7 v30.45,14.7 v38.88,14.7 v46.47,14.7 v54.07,14.7 v61.67,14.7 v69.28,14.7 | v28.3,9.43 28.3,9.6 25.2,9.6 v24.92,9.33
XCKP  (via drill 0.05 pad 0.2)
  Top 0.075: 15.82,16.62 16.02,16.83 16.02,18.05 | 23.42,16.62 23.62,16.83 23.62,18.05 | 31.02,16.62 31.22,16.83 31.22,18.05 | 38.62,16.62 38.82,16.83 38.82,18.05 | 46.22,16.62 46.42,16.83 46.42,18.05 | 53.82,16.62 54.02,16.83 54.02,18.05 | 61.42,16.62 61.62,16.83 61.62,18.05 | 69.03,16.62 69.22,16.83 69.22,18.05 | 17.57,2.98 17.37,2.78 17.37,1.55 | 25.17,2.98 24.97,2.78 24.97,1.55 | 32.77,2.98 32.57,2.78 32.57,1.55 | 40.38,2.98 40.17,2.78 40.17,1.55 | 55.57,2.98 55.38,2.78 55.38,1.55 | 63.17,2.98 62.97,2.78 62.97,1.55 | 70.78,2.98 70.57,2.78 70.57,1.55 | 47.97,2.98 47.77,2.78 47.77,1.55
  Top 0.1: v34.07,4.65 v33.32,4.65 33.12,4.65 32.77,4.3 32.77,2.98 | v25.17,8.55 v25.17,4.65 25.17,2.98 | R15. 26.55,11.48 26.55,13.68 26.32,13.9 v26.32,14.95 | v15.82,14.95 15.82,16.62 | v23.42,14.95 23.42,16.62 | 31.02,16.62 31.02,16.27 30.07,15.33 v30.07,14.95 29.17,14.95 29.17,9.18 28.82,8.83 BARE_DIE.INP v26.92,8.83 26.92,9.05 27.1,9.23 27.7,9.23 | v38.62,14.95 38.62,16.62 | v46.22,14.95 46.22,16.62 | v53.82,14.95 53.82,16.62 | v61.42,14.95 61.42,16.62 | v69.03,14.95 69.03,16.62 | 17.57,2.98 17.57,3.83 v17.65,3.9 | v40.38,4.65 40.38,2.98 | 55.57,2.98 v55.57,4.65 | v63.17,4.65 63.17,2.98 | 70.78,2.98 v70.78,4.65 72.07,4.65 72.85,3.88 73.3,3.88 | v47.97,4.65 47.97,2.98
  Bottom 0.1: v15.82,14.95 v23.42,14.95 v26.32,14.95 v30.07,14.95 v38.62,14.95 v46.22,14.95 v53.82,14.95 v61.42,14.95 v69.03,14.95 | v70.78,4.65 v63.17,4.65 v55.57,4.65 v47.97,4.65 v40.38,4.65 v34.07,4.65 v33.32,4.65 v25.17,4.65 17.95,4.65 17.65,4.35 v17.65,3.9 | v25.17,8.55 25.45,8.83 v26.92,8.83
(copper drawn outside any net)
  shapes: Top circle x2

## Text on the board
Top: 9/01
tNames: TS1 | TV1 | TV8 | TV9 | TV16 | JP1 | TBP | JP2 | TS2 | TS3
Reference: A | B | C | D
tDocu: FE0 | FE7 | FE8 | FE15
